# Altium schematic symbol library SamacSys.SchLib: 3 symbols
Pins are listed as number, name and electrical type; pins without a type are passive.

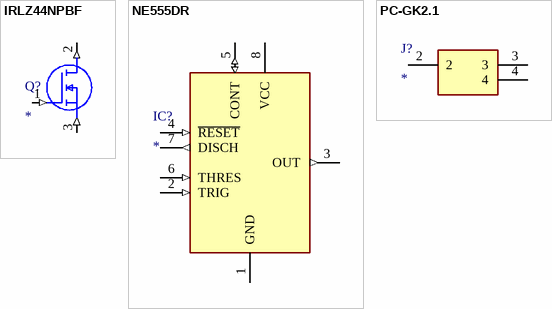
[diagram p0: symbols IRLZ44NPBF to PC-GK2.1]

## IRLZ44NPBF
designator Q?
MOSFET (N-Channel); Manufacturer_Name: Infineon; Manufacturer_Part_Number: IRLZ44NPBF
footprint TO254P469X1042X1967-3P
pins: 1 G (in), 2 D (out), 3 S (in)

## NE555DR
designator IC?
Integrated Circuit; Manufacturer_Name: Texas Instruments; Manufacturer_Part_Number: NE555DR
footprint SOIC127P600X175-8N
pins: 1 GND (power), 2 TRIG (in), 3 OUT (out), 4 ~{RESET} (in), 5 CONT (io), 6 THRES (in), 7 DISCH (out), 8 VCC (power)

## PC-GK2.1
designator J?
Connector; Manufacturer_Name: Ninigi; Manufacturer_Part_Number: PC-GK2.1; Description: Socket; DC supply; male; 5.5/2.1mm; 5.5mm; 2.1mm; THT; angled 90
footprint PCGK21
pins: 2, 3, 4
